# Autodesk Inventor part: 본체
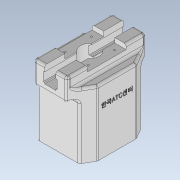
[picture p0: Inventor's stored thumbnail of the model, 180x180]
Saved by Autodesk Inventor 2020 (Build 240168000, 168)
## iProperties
Created: 2023-05
Part Number: 본체
Material: 일반
Document SubType Name: Modeling
Designer: oem
Density: 1 g/cm^3
Appearance: 기본값
Author: oem
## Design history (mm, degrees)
sketch "스케치1"
  geometry: L1 (0, 0)-(0, -80); L2 (0, 0)-(-26.34, 0); L3 (-26.34, 0)-(-35, -15); L4 (-35, -15)-(-35, -65); L5 (-35, -65)-(-26.34, -80); L6 (-26.34, -80)-(0, -80); L7 (35, -65)-(26.34, -80); L8 (35, -15)-(35, -65); L9 (26.34, 0)-(35, -15); L10 (0, 0)-(26.34, 0); L11 (26.34, -80)-(0, -80)
  constraints: 22 end point, 4 symmetric about line, 1 horizontal, 1 parallel, 1 perpendicular, 1 vertical
  dimensions: "d15" = 80 distance of L1.start L1.end; "d16" = 50 distance of L3.end L4.end; "d17" = 60 deg angle of L5 L7; "d18" = 70 distance of L3.end L8.start; "d20" = 60 deg angle of L3 L9; "d21" = 15 vertical distance of L4.end L5.end
extrude "돌출2" new body sketch "스케치1" distance "d22" = 70; taper "d23" = 0 deg
sketch "스케치4"
  geometry: L1 (-26.34, -80)-(-35, -65) reference; L2 (26.34, -80)-(-26.34, -80) reference; L3 (35, -65)-(26.34, -80) reference; L4 (26.34, -80)-(-26.34, -80); L5 (27.494, -78)-(-27.494, -78); L6 (27.494, -78)-(26.34, -80); L7 (-27.494, -78)-(-26.34, -80); 1 further point
  constraints: 8 end point, 3 collinear, 2 point on line, 1 horizontal
  dimensions: "d39" = 2 distance between parallel lines of L5 L2
extrude "돌출3" cut sketch "스케치4" distance "d40" = 64; taper "d41" = 0 deg
sketch "스케치5"
  geometry: L1 (26.34, 0)-(-26.34, 0) reference; L2 (-26.34, 0)-(-35, -15) reference; L3 (-35, -65)-(-26.34, -80) reference; L4 (-26.34, -80)-(26.34, -80) reference; L5 (26.34, -80)-(35, -65) reference; L6 (35, -15)-(26.34, 0) reference; L7 (35, -15)-(26.34, 0) reference; L8 (-26.34, 0)-(-35, -15) reference; L9 (35, -65)-(35, -15) reference; L10 (-35, -15)-(-35, -65) reference; L11 (-35, -15)-(-35, -65); L12 (35, -65)-(35, -15); L13 (35, -65)-(20, -90.981); L14 (20, -90.981)-(-20, -90.981); L15 (-20, -90.981)-(-35, -65); L16 (35, -15)-(19.978, 11.019); L17 (19.978, 11.019)-(-19.978, 11.019); L18 (-19.978, 11.019)-(-35, -15); 9 further points
  constraints: 16 end point, 4 midpoint, 3 collinear, 2 horizontal, 1 vertical alignment
  dimensions: "d65" = 40 distance of L13.end L14.end; "d67" = 60 deg angle of L15 L13; "d71" = 102 distance between parallel lines of L17 L14; "d72" = 60 deg angle of L18 L16
extrude "돌출4" join sketch "스케치5" distance "d73" = 29; taper "d74" = 0 deg
sketch "스케치6"
  geometry: L1 (39.956, 0)-(0, 0) reference; L2 (39.956, -29)-(0, -29) reference; L3 (27.178, -29)-(27.178, -21.482); L4 (27.178, -21.482)-(28.978, -21); L5 (28.978, -21)-(28.978, -10); L6 (28.978, -10)-(27.178, -9.518); L7 (27.178, -9.518)-(27.178, -8); L8 (27.178, -8)-(12.778, -8); L9 (12.778, -8)-(12.778, -9.518); L10 (12.778, -9.518)-(10.978, -10); L11 (10.978, -10)-(10.978, -21); L12 (10.978, -21)-(12.778, -21.482); L13 (12.778, -21.482)-(12.778, -29); L14 (27.178, -29)-(12.778, -29); 5 further points
  constraints: 24 end point, 4 midpoint, 4 parallel, 4 point on line, 3 equal length, 2 perpendicular, 2 vertical, 2 vertical alignment, 1 collinear
  dimensions: "d75" = 14.4 distance between parallel lines of L13 L3; "d76" = 18 distance between parallel lines of L11 L5; "d78" = 11 distance of L10.end L11.end; "d79" = 8 vertical distance of L11.end L13.end; "d80" = 8 vertical distance of L4.end L3.start; "d81" = 30 deg angle of L10 L12; "d82" = 21 distance between parallel lines of L8 L2
extrude "돌출5" cut sketch "스케치6" distance "d83" = 102; taper "d84" = 0 deg
sketch "스케치7"
  geometry: L1 (19.978, 11.019)-(-19.978, 11.019) reference; L2 (35, -65)-(35, -15) reference; L3 (0, -11)-(0, -69); L4 (-6, -11)-(-6, -69); L5 (6, -69)-(6, -11); C1 r 12 at (0, -40); A1 r 6 centre (0, -11) between (6, -11) and (-6, -11); A2 r 6 centre (0, -69) between (-6, -69) and (6, -69); 8 further points
  constraints: 8 end point, 4 point on circle, 4 tangent, 3 centre point, 3 midpoint, 1 coincident, 1 horizontal alignment, 1 parallel, 1 vertical, 1 vertical alignment
  dimensions: "d85" = 24 diameter of C1; "d86" = 58 distance of L3.start L3.end; "d87" = 12 diameter of A2
extrude "돌출6" cut sketch "스케치7" distance "d88" = 30; taper "d89" = 0 deg
sketch "스케치3"
  geometry: L1 (-65, 70)-(-15, 70) reference; L2 (-40, 69)-(-40, 0); L3 (-65, 0)-(-15, 0) reference; L4 (-15, 0)-(-15, 70) reference; L5 (-15, 16)-(-15, 59); L6 (-15, 16)-(-14.272, 14); L7 (-14.272, 14)-(-10, 14); L8 (-10, 14)-(-10, 8); L9 (-10, 8)-(-8.5, 8); L10 (-8.5, 8)-(-8.5, 5.8); L11 (-8.5, 5.8)-(-10, 5.8); L12 (-15, 0)-(0, 0) reference; L13 (-10, 5.8)-(-10, 0); L14 (-10, 0)-(-40, 0); L15 (-15, 59)-(-32, 59); L16 (-32, 59)-(-32, 62.4); L17 (-32, 62.4)-(-30, 62.4); L18 (-30, 62.4)-(-30, 65.6); L19 (-30, 65.6)-(-32, 65.6); L20 (-32, 65.6)-(-32, 69); L21 (-50.392, 69)-(-29.608, 69) reference; L22 (-11, 69)-(-5, 69) reference; 2 further points
  constraints: 32 end point, 9 perpendicular, 5 point on line, 2 horizontal, 2 midpoint, 1 collinear
  dimensions: "d29" = 60 diameter of L8 L2; "d30" = 63 diameter of L10 L2; "d31" = 20 deg angle of L6 L5; "d32" = 2 vertical distance of L6.end L5.start; "d33" = 6 distance of L7.end L8.end; "d34" = 2.2 distance of L9.end L10.end; "d35" = 14 distance from line of L12 L7.end; "d37" = 50 diameter of L5 L2; "d90" = 3.2 distance of L17.end L18.end; "d91" = 16 diameter of L16 L2; "d92" = 20 diameter of L18 L2; "d93" = 45 distance from line of L7.end L15; "d94" = 6.6 distance between parallel lines of L17 L22
revolve "회전1" sketch "스케치3" stored, may be unused: angle "d38" = 90 deg
sketch "스케치10"
  geometry: L1 (20, -90.981)-(35, -65) reference; L2 (35, -65)-(35, -15) reference; L3 (35, -15)-(19.978, 11.019) reference; L4 (7.2, -90.981)-(-7.2, -90.981) reference; L5 (19.978, 11.019)-(-19.978, 11.019) reference; L6 (27.494, -78)-(35, -65) reference; L7 (35, -65)-(35, -15) reference; L8 (35, -65)-(35, -15); L9 (22, -87.517)-(22, 7.517); L10 (35, -65)-(22, -87.517); L11 (26.34, 0)-(19.978, 11.019) reference; L12 (22, 7.517)-(35, -15); 1 further point
  constraints: 8 end point, 3 point on line, 2 vertical, 1 collinear
  dimensions: "d95" = 13 distance between parallel lines of L9 L2
extrude "돌출7" cut sketch "스케치10" distance "d96" = 15; taper "d97" = 0 deg
sketch "스케치12"
  geometry: L1 (54.989, 0)-(0, 0) reference; 5 further points
  constraints: 2 midpoint, 2 vertical alignment
  dimensions: "d107" = 28 distance from line of L1 point (27.494, 28); "d108" = 28 distance of point (27.494, 56) point (27.494, 28)
sketch "스케치13"
  geometry: L1 (-22, -87.517)-(-22, 7.517) reference; L2 (25, -14)-(-25, -14); C1 r 30 at (0, -40) reference; 3 further points
  constraints: 2 end point, 2 vertical alignment, 1 horizontal, 1 midpoint
  dimensions: "d109" = 50 distance of L2.start L2.end; "d110" = 26 distance from line of C1.centre L2
hole "구멍2" sketch "스케치13" at (25, -14), (-25, -14) diameter "d111" = 4.917; stored, may be unused: countersink angle "d115" = 90 deg, drill point angle "d117" = 118 deg; dims "d112" = 12, "d113" = 18, "d114" = 2, "d116" = 14
node "작업 평면1"
chamfer "모따기1" distance "d118" = 1; stored, may be unused: second distance "d119" = 2, angle "d120" = 45 deg
sketch "스케치14"
  geometry: L1 (0, 37.917)-(0, -3.464) reference; L2 (-99, 72.517)-(-99, 22.517) reference; L3 (0, 72.517)-(-6, 72.517); L4 (-6, 72.517)-(-6, 22.517); L5 (-6, 22.517)-(0, 22.517); L6 (0, 22.517)-(0, 72.517); L7 (0, 95.033)-(0, 0) reference; 5 further points
  constraints: 8 end point, 3 midpoint, 2 parallel, 1 horizontal, 1 perpendicular
  dimensions: "d123" = 6 distance of L5.end L4.end; "d124" = 50 distance of L5.end L3.start
extrude "돌출8" cut sketch "스케치14" extent not by distance; stored distance "d125" = 0; taper "d126" = 0 deg
sketch "스케치15"
  geometry: L1 (7.8, -42)-(7.8, -8); A1 r 12 centre (-7.2, -25) between (0, -34.6) and (0, -15.4) reference; 2 further points
  constraints: 2 end point, 1 horizontal alignment, 1 midpoint, 1 vertical
  dimensions: "d127" = 34 distance of L1.start L1.end; "d128" = 15 distance of A1.centre point (7.8, -25)
hole "구멍3" sketch "스케치15" at (7.8, -42), (7.8, -8) diameter "d129" = 2.459; stored, may be unused: countersink angle "d133" = 90 deg, drill point angle "d135" = 118 deg; dims "d130" = 6, "d131" = 18, "d132" = 2, "d134" = 8
fillet "모깎기1" dims "d136" = 3
fillet "모깎기2" dims "d137" = 3
fillet "모깎기3" dims "d138" = 3
fillet "모깎기4" dims "d139" = 3
fillet "모깎기5" dims "d140" = 3
fillet "모깎기6" dims "d141" = 3
fillet "모깎기7" dims "d142" = 0.4
fillet "모깎기8" dims "d143" = 2
chamfer "모따기2" distance "d144" = 1; stored, may be unused: second distance "d145" = 2, angle "d146" = 45 deg
hole "구멍4" sketch "스케치12" diameter "d147" = 8; stored, may be unused: countersink angle "d153" = 82 deg, drill point angle "d155" = 118 deg; dims "d148" = 7.4, "d149" = 0.62479, "d150" = 7.985, "d151" = 3.023, "d152" = 2, "d154" = 11
sketch "스케치16"
  geometry: C1 r 4.224 at (27.494, 56) reference; C2 r 4.224 at (27.494, 28) reference; C3 r 2 at (27.494, 56); C4 r 2 at (27.494, 28); 1 further point
  constraints: 2 centre point, 2 coincident
  dimensions: "d156" = 4 diameter of C3; "d157" = 4 diameter of C4
extrude "돌출9" cut sketch "스케치16" distance "d158" = 15; taper "d159" = 0 deg
fillet "모깎기9" dims "d160" = 3
node "작업 평면2"
sketch "스케치18"
  geometry: L1 (67, 64.196)-(0, 64.196) reference; L2 (99, -22.517)-(99, -0.804) reference; 1 further point
  constraints: 1 other
  dimensions: "d162" = 40 distance from line of point (59, 24.196) L1; "d163" = 40 distance from line of point (59, 24.196) L2
feature "엠보싱1" sketch "스케치18" dims "d164" = 0.5, "d165" = 0
node "솔리드2"
mirror "미러1"
mirror "미러2"
mirror "미러3"
feature "A9D066F2-1C7D-4E18-AEED-F7BC21143FA4" dims "d111" = 4.917, "d112" = 12, "d113" = 18, "d114" = 2, "d115" = 90 deg, "d116" = 14, "d117" = 118 deg
